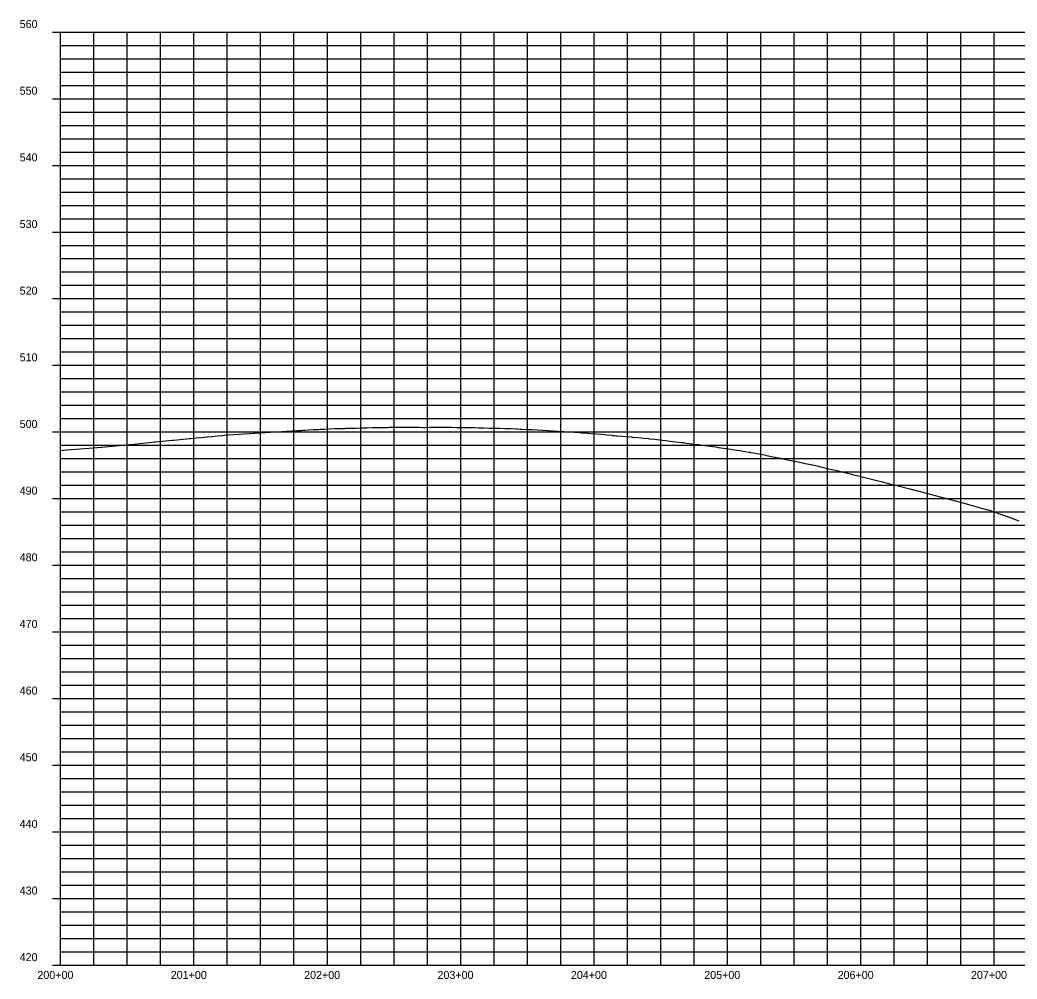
# Model space of a CAD drawing. Extents: x 1054002 to 1056762, y 395173 to 397393.
# Drawn here: x 1054002 to 1054749, y 395173 to 395893 of the extents above; entities that cross this region are included whole.
import ezdxf

# ---------------------------------------------------------------- set-up
doc = ezdxf.new("R2010")
doc.units = 0
for name, color, linetype in [('63', 7, 'Continuous'), ('R_Axis_Annotation', 7, 'Continuous'), ('R_Exist Surface', 7, 'Continuous'), ('R_Grid', 7, 'Continuous'), ('R_Grid Annot', 7, 'Continuous'), ('R_Grid_Minor', 7, 'Continuous')]:
    doc.layers.add(name, color=color, linetype=linetype)

msp = doc.modelspace()

# ---------------------------------------------------------------- linework, layer by layer
at = {"layer": 'R_Exist Surface'}
msp.add_lwpolyline([(1054032.29, 395569.5), (1054037.02, 395569.89), (1054037.11, 395569.9), (1054050.09, 395570.98), (1054050.09, 395570.98), (1054063.07, 395572.06), (1054063.15, 395572.06), (1054076.12, 395573.14), (1054081.23, 395573.66), (1054089.74, 395574.53), (1054102.96, 395575.88), (1054103.64, 395575.96), (1054115.84, 395577.16), (1054117.25, 395577.31), (1054129, 395578.47), (1054129.97, 395578.57), (1054133.97, 395578.96), (1054137.96, 395579.34), (1054139.78, 395579.51), (1054141.95, 395579.74), (1054142.48, 395579.8), (1054145.95, 395580.12), (1054149.94, 395580.48), (1054153.2, 395580.76), (1054153.94, 395580.83), (1054155.19, 395580.95), (1054157.93, 395581.15), (1054161.93, 395581.45), (1054165.92, 395581.73), (1054169.92, 395582.01), (1054173.91, 395582.28), (1054174.43, 395582.31), (1054176.94, 395582.51), (1054177.91, 395582.59), (1054179.33, 395582.7), (1054181.9, 395582.86), (1054185.89, 395583.09), (1054189.89, 395583.32), (1054193.88, 395583.53), (1054197.88, 395583.73), (1054199.97, 395583.83), (1054201.33, 395583.92), (1054201.87, 395583.96), (1054205.87, 395584.21), (1054209.86, 395584.46), (1054212.62, 395584.62), (1054213.86, 395584.71), (1054215.42, 395584.82), (1054217.85, 395584.95), (1054221.85, 395585.16), (1054225.84, 395585.36), (1054226.96, 395585.41), (1054229.11, 395585.54), (1054229.83, 395585.57), (1054233.83, 395585.73), (1054237.82, 395585.88), (1054240.59, 395585.97), (1054241.82, 395586.01), (1054245.58, 395586.12), (1054245.81, 395586.13), (1054249.81, 395586.22), (1054253.17, 395586.29), (1054253.8, 395586.31), (1054253.93, 395586.32), (1054257.8, 395586.45), (1054261.79, 395586.56), (1054265.79, 395586.66), (1054266, 395586.67), (1054266.35, 395586.68), (1054269.78, 395586.75), (1054273.77, 395586.82), (1054277.77, 395586.87), (1054278.8, 395586.88), (1054279.22, 395586.89), (1054281.76, 395586.91), (1054285.76, 395586.94), (1054289.75, 395586.94), (1054291.59, 395586.94), (1054292.6, 395586.94), (1054293.75, 395586.94), (1054297.74, 395586.92), (1054301.74, 395586.88), (1054304.41, 395586.84), (1054305.73, 395586.86), (1054309.73, 395586.9), (1054313.72, 395586.92), (1054315.78, 395586.92), (1054317.71, 395586.94), (1054317.97, 395586.94), (1054321.71, 395586.93), (1054325.7, 395586.91), (1054329.5, 395586.87), (1054329.7, 395586.87), (1054333.69, 395586.81), (1054337.69, 395586.74), (1054341.2, 395586.67), (1054341.68, 395586.66), (1054343.07, 395586.64), (1054345.68, 395586.57), (1054349.67, 395586.46), (1054353.67, 395586.34), (1054354.65, 395586.3), (1054357.66, 395586.24), (1054361.65, 395586.13), (1054365.65, 395586.01), (1054369.64, 395585.88), (1054373.64, 395585.74), (1054374.88, 395585.69), (1054376.9, 395585.55), (1054377.63, 395585.52), (1054377.9, 395585.51), (1054381.63, 395585.35), (1054385.62, 395585.15), (1054389.62, 395584.95), (1054393.61, 395584.72), (1054397.61, 395584.48), (1054397.82, 395584.47), (1054399.61, 395584.35), (1054401.6, 395584.25), (1054405.59, 395584.03), (1054409.59, 395583.79), (1054413.58, 395583.54), (1054417.58, 395583.26), (1054421.57, 395582.98), (1054422.12, 395582.94), (1054422.92, 395582.87), (1054423.79, 395582.79), (1054425.57, 395582.65), (1054429.56, 395582.33), (1054433.56, 395582), (1054437.55, 395581.64), (1054441.55, 395581.27), (1054445.54, 395580.88), (1054446.01, 395580.83), (1054447.5, 395580.71), (1054448.86, 395580.6), (1054449.53, 395580.55), (1054453.53, 395580.22), (1054457.52, 395579.88), (1054460.28, 395579.63), (1054460.85, 395579.58), (1054461.52, 395579.52), (1054465.51, 395579.14), (1054469.51, 395578.75), (1054473.03, 395578.39), (1054473.17, 395578.38), (1054473.5, 395578.34), (1054477.5, 395577.92), (1054481.49, 395577.48), (1054485.49, 395577.02), (1054485.73, 395577), (1054485.88, 395576.98), (1054489.48, 395576.56), (1054493.47, 395576.07), (1054497.47, 395575.57), (1054498.4, 395575.45), (1054498.97, 395575.39), (1054501.46, 395575.09), (1054505.28, 395574.62), (1054505.46, 395574.59), (1054509.45, 395574.08), (1054510.95, 395573.88), (1054511.4, 395573.82), (1054513.45, 395573.54), (1054517.44, 395573), (1054521.44, 395572.44), (1054523.46, 395572.15), (1054524.54, 395571.98), (1054525.43, 395571.86), (1054529.43, 395571.27), (1054533.42, 395570.67), (1054536.02, 395570.28), (1054537.25, 395570.08), (1054537.41, 395570.05), (1054541.41, 395569.43), (1054545.4, 395568.8), (1054548.66, 395568.27), (1054549.4, 395568.14), (1054549.57, 395568.11), (1054553.39, 395567.4), (1054557.39, 395566.65), (1054561.38, 395565.89), (1054561.44, 395565.87), (1054563.06, 395565.52), (1054565.38, 395565.06), (1054569.37, 395564.27), (1054573.37, 395563.47), (1054574.37, 395563.27), (1054576.19, 395562.85), (1054577.36, 395562.62), (1054581.35, 395561.8), (1054585.35, 395560.97), (1054587.43, 395560.54), (1054588.92, 395560.19), (1054589.34, 395560.1), (1054593.34, 395559.26), (1054597.33, 395558.42), (1054600.61, 395557.73), (1054601.24, 395557.57), (1054601.33, 395557.55), (1054605.32, 395556.58), (1054609.32, 395555.61), (1054613.31, 395554.63), (1054617.31, 395553.64), (1054619.26, 395553.16), (1054621.3, 395552.65), (1054624.93, 395551.74), (1054625.29, 395551.66), (1054625.3, 395551.66), (1054625.74, 395551.57), (1054629.29, 395550.69), (1054633.28, 395549.7), (1054637.28, 395548.71), (1054641.27, 395547.72), (1054645.27, 395546.72), (1054647.53, 395546.15), (1054649.26, 395545.71), (1054653.26, 395544.67), (1054653.72, 395544.55), (1054657.25, 395543.67), (1054669.15, 395540.69), (1054682.54, 395537.16), (1054690.89, 395535.04), (1054700.22, 395532.51), (1054702.38, 395531.91), (1054713.38, 395528.94), (1054713.81, 395528.82), (1054716.61, 395528.07), (1054727.37, 395525.07), (1054727.65, 395524.99), (1054727.88, 395524.92), (1054742.71, 395519.64), (1054750.85, 395516.73)], dxfattribs=at)
at = {"layer": 'R_Grid'}
for p, q in [((1054032.29, 395183.41), (1054032.29, 395883.41)), ((1054032.29, 395883.41), (1056732.29, 395883.41)), ((1054032.29, 395883.41), (1056732.29, 395883.41)), ((1054132.29, 395183.41), (1054132.29, 395883.41)), ((1054232.29, 395183.41), (1054232.29, 395883.41)), ((1054332.29, 395183.41), (1054332.29, 395883.41)), ((1054432.29, 395183.41), (1054432.29, 395883.41)), ((1054532.29, 395183.41), (1054532.29, 395883.41)), ((1054632.29, 395183.41), (1054632.29, 395883.41)), ((1054732.29, 395183.41), (1054732.29, 395883.41)), ((1054032.29, 395833.41), (1056732.29, 395833.41)), ((1054032.29, 395783.41), (1056732.29, 395783.41)), ((1054032.29, 395733.41), (1056732.29, 395733.41)), ((1054032.29, 395683.41), (1056732.29, 395683.41)), ((1054032.29, 395633.41), (1056732.29, 395633.41)), ((1054032.29, 395583.41), (1056732.29, 395583.41)), ((1054032.29, 395533.41), (1056732.29, 395533.41)), ((1054032.29, 395483.41), (1056732.29, 395483.41)), ((1054032.29, 395433.41), (1056732.29, 395433.41)), ((1054032.29, 395383.41), (1056732.29, 395383.41)), ((1054032.29, 395333.41), (1056732.29, 395333.41)), ((1054032.29, 395283.41), (1056732.29, 395283.41)), ((1054032.29, 395233.41), (1056732.29, 395233.41)), ((1054032.29, 395183.41), (1056732.29, 395183.41))]:
    msp.add_line(p, q, dxfattribs=at)
at = {"layer": 'R_Grid Annot'}
for p, q in [((1054026.29, 395883.41), (1054032.29, 395883.41)), ((1054026.29, 395883.41), (1054032.29, 395883.41)), ((1054032.29, 395873.41), (1054035.29, 395873.41)), ((1054032.29, 395863.41), (1054035.29, 395863.41)), ((1054032.29, 395853.41), (1054035.29, 395853.41)), ((1054032.29, 395843.41), (1054035.29, 395843.41)), ((1054026.29, 395833.41), (1054032.29, 395833.41)), ((1054032.29, 395823.41), (1054035.29, 395823.41)), ((1054032.29, 395813.41), (1054035.29, 395813.41)), ((1054032.29, 395803.41), (1054035.29, 395803.41)), ((1054032.29, 395793.41), (1054035.29, 395793.41)), ((1054026.29, 395783.41), (1054032.29, 395783.41)), ((1054032.29, 395773.41), (1054035.29, 395773.41)), ((1054032.29, 395763.41), (1054035.29, 395763.41)), ((1054032.29, 395753.41), (1054035.29, 395753.41)), ((1054032.29, 395743.41), (1054035.29, 395743.41)), ((1054026.29, 395733.41), (1054032.29, 395733.41)), ((1054032.29, 395723.41), (1054035.29, 395723.41)), ((1054032.29, 395713.41), (1054035.29, 395713.41)), ((1054032.29, 395703.41), (1054035.29, 395703.41)), ((1054032.29, 395693.41), (1054035.29, 395693.41)), ((1054026.29, 395683.41), (1054032.29, 395683.41)), ((1054032.29, 395673.41), (1054035.29, 395673.41)), ((1054032.29, 395663.41), (1054035.29, 395663.41)), ((1054032.29, 395653.41), (1054035.29, 395653.41)), ((1054032.29, 395643.41), (1054035.29, 395643.41)), ((1054026.29, 395633.41), (1054032.29, 395633.41)), ((1054032.29, 395623.41), (1054035.29, 395623.41)), ((1054032.29, 395613.41), (1054035.29, 395613.41)), ((1054032.29, 395603.41), (1054035.29, 395603.41)), ((1054032.29, 395593.41), (1054035.29, 395593.41)), ((1054026.29, 395583.41), (1054032.29, 395583.41)), ((1054032.29, 395573.41), (1054035.29, 395573.41)), ((1054032.29, 395563.41), (1054035.29, 395563.41)), ((1054032.29, 395553.41), (1054035.29, 395553.41)), ((1054032.29, 395543.41), (1054035.29, 395543.41)), ((1054026.29, 395533.41), (1054032.29, 395533.41)), ((1054032.29, 395523.41), (1054035.29, 395523.41)), ((1054032.29, 395513.41), (1054035.29, 395513.41)), ((1054032.29, 395503.41), (1054035.29, 395503.41)), ((1054032.29, 395493.41), (1054035.29, 395493.41)), ((1054026.29, 395483.41), (1054032.29, 395483.41)), ((1054032.29, 395473.41), (1054035.29, 395473.41)), ((1054032.29, 395463.41), (1054035.29, 395463.41)), ((1054032.29, 395453.41), (1054035.29, 395453.41)), ((1054032.29, 395443.41), (1054035.29, 395443.41)), ((1054026.29, 395433.41), (1054032.29, 395433.41)), ((1054032.29, 395423.41), (1054035.29, 395423.41)), ((1054032.29, 395413.41), (1054035.29, 395413.41)), ((1054032.29, 395403.41), (1054035.29, 395403.41)), ((1054032.29, 395393.41), (1054035.29, 395393.41)), ((1054026.29, 395383.41), (1054032.29, 395383.41)), ((1054032.29, 395373.41), (1054035.29, 395373.41)), ((1054032.29, 395363.41), (1054035.29, 395363.41)), ((1054032.29, 395353.41), (1054035.29, 395353.41)), ((1054032.29, 395343.41), (1054035.29, 395343.41)), ((1054026.29, 395333.41), (1054032.29, 395333.41)), ((1054032.29, 395323.41), (1054035.29, 395323.41)), ((1054032.29, 395313.41), (1054035.29, 395313.41)), ((1054032.29, 395303.41), (1054035.29, 395303.41)), ((1054032.29, 395293.41), (1054035.29, 395293.41)), ((1054026.29, 395283.41), (1054032.29, 395283.41)), ((1054032.29, 395273.41), (1054035.29, 395273.41)), ((1054032.29, 395263.41), (1054035.29, 395263.41)), ((1054032.29, 395253.41), (1054035.29, 395253.41)), ((1054032.29, 395243.41), (1054035.29, 395243.41)), ((1054026.29, 395233.41), (1054032.29, 395233.41)), ((1054032.29, 395223.41), (1054035.29, 395223.41)), ((1054032.29, 395213.41), (1054035.29, 395213.41)), ((1054032.29, 395203.41), (1054035.29, 395203.41)), ((1054032.29, 395193.41), (1054035.29, 395193.41)), ((1054026.29, 395183.41), (1054032.29, 395183.41))]:
    msp.add_line(p, q, dxfattribs=at)
at = {"layer": 'R_Grid_Minor'}
for p, q in [((1054057.29, 395183.41), (1054057.29, 395883.41)), ((1054082.29, 395183.41), (1054082.29, 395883.41)), ((1054107.29, 395183.41), (1054107.29, 395883.41)), ((1054157.29, 395183.41), (1054157.29, 395883.41)), ((1054182.29, 395183.41), (1054182.29, 395883.41)), ((1054207.29, 395183.41), (1054207.29, 395883.41)), ((1054257.29, 395183.41), (1054257.29, 395883.41)), ((1054282.29, 395183.41), (1054282.29, 395883.41)), ((1054307.29, 395183.41), (1054307.29, 395883.41)), ((1054357.29, 395183.41), (1054357.29, 395883.41)), ((1054382.29, 395183.41), (1054382.29, 395883.41)), ((1054407.29, 395183.41), (1054407.29, 395883.41)), ((1054457.29, 395183.41), (1054457.29, 395883.41)), ((1054482.29, 395183.41), (1054482.29, 395883.41)), ((1054507.29, 395183.41), (1054507.29, 395883.41)), ((1054557.29, 395183.41), (1054557.29, 395883.41)), ((1054582.29, 395183.41), (1054582.29, 395883.41)), ((1054607.29, 395183.41), (1054607.29, 395883.41)), ((1054657.29, 395183.41), (1054657.29, 395883.41)), ((1054682.29, 395183.41), (1054682.29, 395883.41)), ((1054707.29, 395183.41), (1054707.29, 395883.41)), ((1054032.29, 395873.41), (1056732.29, 395873.41)), ((1054032.29, 395863.41), (1056732.29, 395863.41)), ((1054032.29, 395853.41), (1056732.29, 395853.41)), ((1054032.29, 395843.41), (1056732.29, 395843.41)), ((1054032.29, 395823.41), (1056732.29, 395823.41)), ((1054032.29, 395813.41), (1056732.29, 395813.41)), ((1054032.29, 395803.41), (1056732.29, 395803.41)), ((1054032.29, 395793.41), (1056732.29, 395793.41)), ((1054032.29, 395773.41), (1056732.29, 395773.41)), ((1054032.29, 395763.41), (1056732.29, 395763.41)), ((1054032.29, 395753.41), (1056732.29, 395753.41)), ((1054032.29, 395743.41), (1056732.29, 395743.41)), ((1054032.29, 395723.41), (1056732.29, 395723.41)), ((1054032.29, 395713.41), (1056732.29, 395713.41)), ((1054032.29, 395703.41), (1056732.29, 395703.41)), ((1054032.29, 395693.41), (1056732.29, 395693.41)), ((1054032.29, 395673.41), (1056732.29, 395673.41)), ((1054032.29, 395663.41), (1056732.29, 395663.41)), ((1054032.29, 395653.41), (1056732.29, 395653.41)), ((1054032.29, 395643.41), (1056732.29, 395643.41)), ((1054032.29, 395623.41), (1056732.29, 395623.41)), ((1054032.29, 395613.41), (1056732.29, 395613.41)), ((1054032.29, 395603.41), (1056732.29, 395603.41)), ((1054032.29, 395593.41), (1056732.29, 395593.41)), ((1054032.29, 395573.41), (1056732.29, 395573.41)), ((1054032.29, 395563.41), (1056732.29, 395563.41)), ((1054032.29, 395553.41), (1056732.29, 395553.41)), ((1054032.29, 395543.41), (1056732.29, 395543.41)), ((1054032.29, 395523.41), (1056732.29, 395523.41)), ((1054032.29, 395513.41), (1056732.29, 395513.41)), ((1054032.29, 395503.41), (1056732.29, 395503.41)), ((1054032.29, 395493.41), (1056732.29, 395493.41)), ((1054032.29, 395473.41), (1056732.29, 395473.41)), ((1054032.29, 395463.41), (1056732.29, 395463.41)), ((1054032.29, 395453.41), (1056732.29, 395453.41)), ((1054032.29, 395443.41), (1056732.29, 395443.41)), ((1054032.29, 395423.41), (1056732.29, 395423.41)), ((1054032.29, 395413.41), (1056732.29, 395413.41)), ((1054032.29, 395403.41), (1056732.29, 395403.41)), ((1054032.29, 395393.41), (1056732.29, 395393.41)), ((1054032.29, 395373.41), (1056732.29, 395373.41)), ((1054032.29, 395363.41), (1056732.29, 395363.41)), ((1054032.29, 395353.41), (1056732.29, 395353.41)), ((1054032.29, 395343.41), (1056732.29, 395343.41)), ((1054032.29, 395323.41), (1056732.29, 395323.41)), ((1054032.29, 395313.41), (1056732.29, 395313.41)), ((1054032.29, 395303.41), (1056732.29, 395303.41)), ((1054032.29, 395293.41), (1056732.29, 395293.41)), ((1054032.29, 395273.41), (1056732.29, 395273.41)), ((1054032.29, 395263.41), (1056732.29, 395263.41)), ((1054032.29, 395253.41), (1056732.29, 395253.41)), ((1054032.29, 395243.41), (1056732.29, 395243.41)), ((1054032.29, 395223.41), (1056732.29, 395223.41)), ((1054032.29, 395213.41), (1056732.29, 395213.41)), ((1054032.29, 395203.41), (1056732.29, 395203.41)), ((1054032.29, 395193.41), (1056732.29, 395193.41))]:
    msp.add_line(p, q, dxfattribs=at)

# ---------------------------------------------------------------- texts
at = {"layer": '63'}
msp.add_text('-', height=0.0001, dxfattribs=at).set_placement((1054032.29, 395183.41))
at = {"layer": 'R_Axis_Annotation'}
for s, p in [('560', (1054001.62, 395886.41)), ('560', (1054001.62, 395886.41)), ('550', (1054001.62, 395836.41)), ('540', (1054001.62, 395786.41)), ('530', (1054001.62, 395736.41)), ('520', (1054001.62, 395686.41)), ('510', (1054001.62, 395636.41)), ('500', (1054001.62, 395586.41)), ('490', (1054001.62, 395536.41)), ('480', (1054001.62, 395486.41)), ('470', (1054001.62, 395436.41)), ('460', (1054001.62, 395386.41)), ('450', (1054001.62, 395336.41)), ('440', (1054001.62, 395286.41)), ('430', (1054001.62, 395236.41)), ('420', (1054001.62, 395186.41)), ('200+00', (1054014.89, 395173.06)), ('201+00', (1054114.89, 395173.06)), ('202+00', (1054214.89, 395173.06)), ('203+00', (1054314.89, 395173.06)), ('204+00', (1054414.89, 395173.06)), ('205+00', (1054514.89, 395173.06)), ('206+00', (1054614.89, 395173.06)), ('207+00', (1054714.89, 395173.06))]:
    msp.add_text(s, height=6, dxfattribs=at).set_placement(p)

doc.saveas('drawing.dxf')
